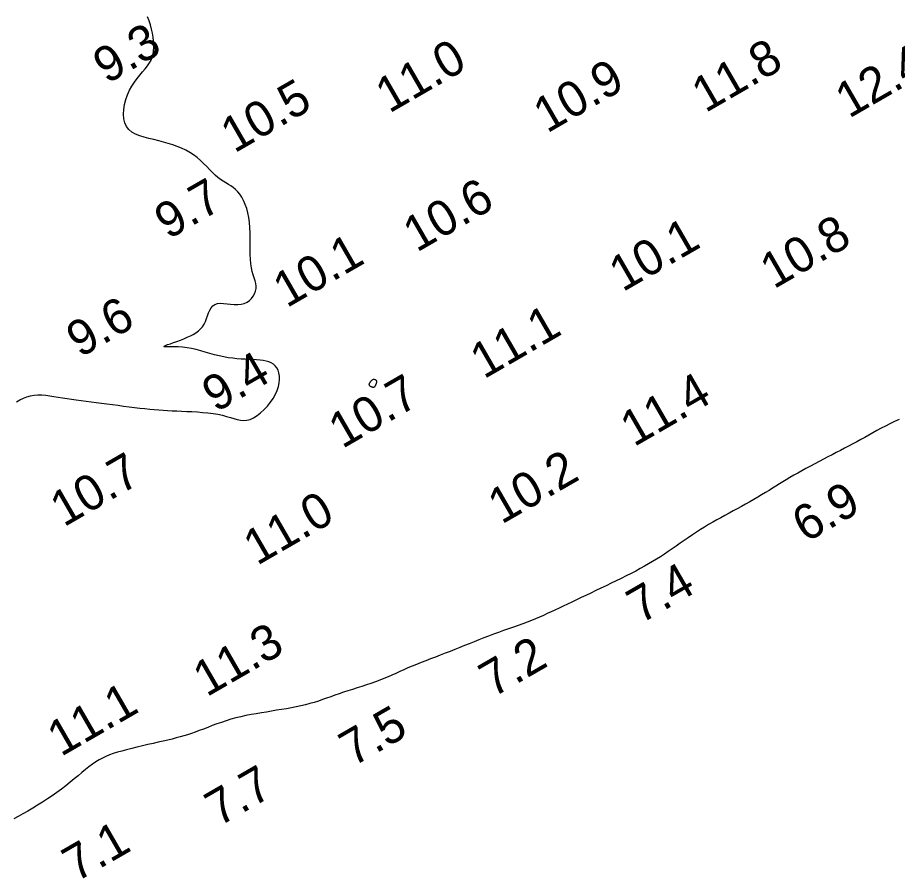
# Model space of a CAD drawing. Extents: x 3024098 to 3056816, y 418252 to 509144.
# Drawn here: x 3024802.5 to 3024927, y 428293.1 to 428414.9 of the extents above; entities that cross this region are included whole.
import ezdxf

# ---------------------------------------------------------------- set-up
doc = ezdxf.new("R2010")
doc.units = 0
doc.layers.add('V-CHAN-CONT-EL10', color=7, linetype='Continuous')
doc.layers.add('V-TOPO-SOUN-0911', color=7, linetype='Continuous')

msp = doc.modelspace()

# ---------------------------------------------------------------- linework, layer by layer
at = {"layer": 'V-CHAN-CONT-EL10'}
for points in [[(3024802.33, 428360.55), (3024802.82, 428360.83), (3024803.31, 428361.08), (3024803.81, 428361.28), (3024804.32, 428361.43), (3024804.84, 428361.52), (3024805.37, 428361.56), (3024805.91, 428361.55), (3024806.47, 428361.5), (3024807.05, 428361.42), (3024807.63, 428361.33), (3024808.23, 428361.23), (3024808.85, 428361.12), (3024809.48, 428361.02), (3024810.13, 428360.92), (3024810.79, 428360.84), (3024811.47, 428360.75), (3024812.17, 428360.66), (3024812.88, 428360.57), (3024813.61, 428360.48), (3024814.36, 428360.39), (3024815.13, 428360.28), (3024815.92, 428360.18), (3024816.71, 428360.07), (3024817.49, 428359.96), (3024818.27, 428359.86), (3024819.04, 428359.76), (3024819.78, 428359.67), (3024820.5, 428359.59), (3024821.18, 428359.52), (3024821.83, 428359.46), (3024822.47, 428359.42), (3024823.09, 428359.37), (3024823.72, 428359.34), (3024824.36, 428359.3), (3024825.01, 428359.27), (3024825.7, 428359.24), (3024826.42, 428359.21), (3024827.16, 428359.17), (3024827.92, 428359.12), (3024828.67, 428359.06), (3024829.42, 428358.99), (3024830.14, 428358.9), (3024830.83, 428358.79), (3024831.47, 428358.66), (3024832.05, 428358.5), (3024832.59, 428358.34), (3024833.09, 428358.18), (3024833.56, 428358.05), (3024834.02, 428357.96), (3024834.46, 428357.92), (3024834.92, 428357.96), (3024835.39, 428358.08), (3024835.88, 428358.3), (3024836.38, 428358.62), (3024836.88, 428359.01), (3024837.38, 428359.46), (3024837.84, 428359.96), (3024838.27, 428360.5), (3024838.66, 428361.05), (3024838.98, 428361.62), (3024839.22, 428362.18), (3024839.4, 428362.72), (3024839.51, 428363.24), (3024839.56, 428363.74), (3024839.54, 428364.21), (3024839.47, 428364.64), (3024839.35, 428365.03), (3024839.17, 428365.36), (3024838.95, 428365.65), (3024838.69, 428365.88), (3024838.38, 428366.06), (3024838.04, 428366.21), (3024837.66, 428366.32), (3024837.24, 428366.4), (3024836.79, 428366.46), (3024836.31, 428366.5), (3024835.8, 428366.54), (3024835.26, 428366.56), (3024834.7, 428366.59), (3024834.12, 428366.62), (3024833.53, 428366.66), (3024832.92, 428366.72), (3024832.29, 428366.8), (3024831.65, 428366.92), (3024831.01, 428367.06), (3024830.36, 428367.23), (3024829.7, 428367.41), (3024829.05, 428367.6), (3024828.4, 428367.79), (3024827.74, 428367.96), (3024827.1, 428368.11), (3024826.46, 428368.22), (3024825.83, 428368.29), (3024825.23, 428368.33), (3024824.68, 428368.34), (3024824.19, 428368.34), (3024823.77, 428368.33), (3024823.45, 428368.33), (3024823.25, 428368.34), (3024823.17, 428368.38), (3024823.24, 428368.44), (3024823.43, 428368.53), (3024823.72, 428368.65), (3024824.1, 428368.79), (3024824.54, 428368.95), (3024825.02, 428369.12), (3024825.52, 428369.3), (3024826.02, 428369.49), (3024826.49, 428369.69), (3024826.93, 428369.89), (3024827.35, 428370.1), (3024827.73, 428370.33), (3024828.08, 428370.59), (3024828.39, 428370.87), (3024828.67, 428371.18), (3024828.89, 428371.53), (3024829.08, 428371.92), (3024829.24, 428372.33), (3024829.38, 428372.75), (3024829.52, 428373.16), (3024829.68, 428373.54), (3024829.87, 428373.88), (3024830.1, 428374.15), (3024830.39, 428374.35), (3024830.75, 428374.46), (3024831.16, 428374.5), (3024831.62, 428374.48), (3024832.12, 428374.44), (3024832.63, 428374.38), (3024833.14, 428374.34), (3024833.64, 428374.33), (3024834.12, 428374.37), (3024834.56, 428374.49), (3024834.95, 428374.67), (3024835.3, 428374.91), (3024835.6, 428375.19), (3024835.84, 428375.51), (3024836.03, 428375.85), (3024836.16, 428376.21), (3024836.23, 428376.58), (3024836.23, 428376.94), (3024836.18, 428377.31), (3024836.08, 428377.69), (3024835.97, 428378.09), (3024835.83, 428378.53), (3024835.7, 428379), (3024835.58, 428379.52), (3024835.49, 428380.09), (3024835.43, 428380.73), (3024835.4, 428381.42), (3024835.4, 428382.15), (3024835.4, 428382.91), (3024835.4, 428383.68), (3024835.39, 428384.45), (3024835.36, 428385.21), (3024835.3, 428385.95), (3024835.2, 428386.65), (3024835.07, 428387.32), (3024834.9, 428387.94), (3024834.7, 428388.51), (3024834.47, 428389.04), (3024834.21, 428389.52), (3024833.94, 428389.94), (3024833.64, 428390.3), (3024833.33, 428390.61), (3024833.01, 428390.88), (3024832.67, 428391.11), (3024832.32, 428391.33), (3024831.96, 428391.54), (3024831.59, 428391.77), (3024831.22, 428392.02), (3024830.84, 428392.3), (3024830.46, 428392.64), (3024830.06, 428393.02), (3024829.66, 428393.43), (3024829.25, 428393.85), (3024828.81, 428394.29), (3024828.36, 428394.72), (3024827.88, 428395.13), (3024827.38, 428395.52), (3024826.84, 428395.86), (3024826.28, 428396.18), (3024825.69, 428396.46), (3024825.08, 428396.71), (3024824.45, 428396.94), (3024823.79, 428397.14), (3024823.13, 428397.33), (3024822.45, 428397.51), (3024821.76, 428397.67), (3024821.07, 428397.83), (3024820.4, 428398.01), (3024819.77, 428398.21), (3024819.19, 428398.46), (3024818.67, 428398.75), (3024818.23, 428399.1), (3024817.88, 428399.54), (3024817.64, 428400.05), (3024817.5, 428400.63), (3024817.46, 428401.27), (3024817.5, 428401.94), (3024817.61, 428402.63), (3024817.79, 428403.33), (3024818.04, 428404), (3024818.33, 428404.65), (3024818.66, 428405.24), (3024819.03, 428405.79), (3024819.41, 428406.31), (3024819.79, 428406.79), (3024820.17, 428407.25), (3024820.53, 428407.68), (3024820.86, 428408.11), (3024821.14, 428408.53), (3024821.37, 428408.94), (3024821.54, 428409.36), (3024821.66, 428409.79), (3024821.74, 428410.23), (3024821.77, 428410.69), (3024821.77, 428411.16), (3024821.73, 428411.66), (3024821.66, 428412.19), (3024821.57, 428412.74), (3024821.44, 428413.32), (3024821.29, 428413.9), (3024821.1, 428414.47), (3024820.87, 428415.03)], [(3024927.21, 428358.08), (3024926.55, 428357.77), (3024925.92, 428357.45), (3024925.3, 428357.13), (3024924.69, 428356.81), (3024924.09, 428356.48), (3024923.51, 428356.16), (3024922.93, 428355.84), (3024922.36, 428355.52), (3024921.79, 428355.21), (3024921.22, 428354.9), (3024920.65, 428354.6), (3024920.08, 428354.29), (3024919.5, 428353.99), (3024918.92, 428353.68), (3024918.33, 428353.38), (3024917.74, 428353.07), (3024917.13, 428352.76), (3024916.52, 428352.44), (3024915.9, 428352.11), (3024915.28, 428351.78), (3024914.66, 428351.46), (3024914.04, 428351.13), (3024913.45, 428350.8), (3024912.87, 428350.48), (3024912.31, 428350.16), (3024911.77, 428349.84), (3024911.26, 428349.54), (3024910.77, 428349.23), (3024910.28, 428348.93), (3024909.79, 428348.63), (3024909.31, 428348.32), (3024908.81, 428348.02), (3024908.3, 428347.71), (3024907.77, 428347.39), (3024907.22, 428347.07), (3024906.66, 428346.74), (3024906.08, 428346.41), (3024905.5, 428346.08), (3024904.91, 428345.76), (3024904.32, 428345.43), (3024903.73, 428345.11), (3024903.15, 428344.79), (3024902.57, 428344.47), (3024901.99, 428344.16), (3024901.42, 428343.84), (3024900.84, 428343.51), (3024900.27, 428343.18), (3024899.7, 428342.83), (3024899.12, 428342.47), (3024898.55, 428342.1), (3024897.97, 428341.72), (3024897.39, 428341.32), (3024896.82, 428340.93), (3024896.25, 428340.53), (3024895.68, 428340.13), (3024895.12, 428339.74), (3024894.56, 428339.36), (3024894, 428339), (3024893.45, 428338.64), (3024892.9, 428338.3), (3024892.34, 428337.96), (3024891.77, 428337.62), (3024891.18, 428337.29), (3024890.58, 428336.95), (3024889.95, 428336.61), (3024889.29, 428336.27), (3024888.61, 428335.92), (3024887.91, 428335.57), (3024887.19, 428335.22), (3024886.47, 428334.87), (3024885.75, 428334.52), (3024885.02, 428334.17), (3024884.31, 428333.83), (3024883.6, 428333.49), (3024882.91, 428333.16), (3024882.23, 428332.84), (3024881.57, 428332.53), (3024880.92, 428332.22), (3024880.29, 428331.92), (3024879.69, 428331.64), (3024879.1, 428331.36), (3024878.52, 428331.09), (3024877.97, 428330.83), (3024877.42, 428330.58), (3024876.88, 428330.33), (3024876.33, 428330.09), (3024875.77, 428329.85), (3024875.19, 428329.61), (3024874.59, 428329.38), (3024873.97, 428329.14), (3024873.31, 428328.9), (3024872.64, 428328.66), (3024871.95, 428328.42), (3024871.25, 428328.17), (3024870.55, 428327.92), (3024869.84, 428327.67), (3024869.14, 428327.41), (3024868.45, 428327.14), (3024867.76, 428326.87), (3024867.08, 428326.6), (3024866.4, 428326.32), (3024865.72, 428326.05), (3024865.04, 428325.77), (3024864.36, 428325.5), (3024863.68, 428325.23), (3024862.99, 428324.96), (3024862.29, 428324.7), (3024861.6, 428324.43), (3024860.92, 428324.17), (3024860.24, 428323.92), (3024859.58, 428323.66), (3024858.94, 428323.4), (3024858.31, 428323.15), (3024857.72, 428322.89), (3024857.14, 428322.63), (3024856.58, 428322.37), (3024856.02, 428322.12), (3024855.46, 428321.86), (3024854.9, 428321.62), (3024854.33, 428321.38), (3024853.74, 428321.14), (3024853.12, 428320.92), (3024852.48, 428320.7), (3024851.84, 428320.48), (3024851.18, 428320.28), (3024850.52, 428320.07), (3024849.86, 428319.86), (3024849.22, 428319.65), (3024848.59, 428319.45), (3024847.97, 428319.23), (3024847.38, 428319.02), (3024846.79, 428318.81), (3024846.21, 428318.6), (3024845.63, 428318.4), (3024845.05, 428318.2), (3024844.45, 428318.01), (3024843.85, 428317.84), (3024843.22, 428317.67), (3024842.57, 428317.52), (3024841.91, 428317.38), (3024841.24, 428317.25), (3024840.55, 428317.12), (3024839.85, 428317), (3024839.14, 428316.89), (3024838.42, 428316.77), (3024837.7, 428316.65), (3024836.98, 428316.53), (3024836.25, 428316.41), (3024835.52, 428316.28), (3024834.8, 428316.14), (3024834.08, 428315.98), (3024833.38, 428315.81), (3024832.68, 428315.62), (3024831.99, 428315.41), (3024831.32, 428315.19), (3024830.66, 428314.96), (3024830.02, 428314.72), (3024829.39, 428314.48), (3024828.78, 428314.24), (3024828.19, 428314.02), (3024827.62, 428313.81), (3024827.08, 428313.61), (3024826.54, 428313.44), (3024826.01, 428313.28), (3024825.47, 428313.12), (3024824.92, 428312.98), (3024824.34, 428312.83), (3024823.73, 428312.68), (3024823.09, 428312.53), (3024822.39, 428312.37), (3024821.66, 428312.21), (3024820.91, 428312.04), (3024820.14, 428311.86), (3024819.38, 428311.68), (3024818.63, 428311.5), (3024817.91, 428311.32), (3024817.23, 428311.13), (3024816.61, 428310.95), (3024816.03, 428310.76), (3024815.49, 428310.57), (3024814.98, 428310.36), (3024814.49, 428310.13), (3024814.02, 428309.87), (3024813.55, 428309.59), (3024813.07, 428309.27), (3024812.59, 428308.91), (3024812.09, 428308.51), (3024811.57, 428308.09), (3024811.04, 428307.64), (3024810.49, 428307.18), (3024809.92, 428306.7), (3024809.32, 428306.22), (3024808.7, 428305.74), (3024808.05, 428305.26), (3024807.38, 428304.8), (3024806.7, 428304.34), (3024806.01, 428303.89), (3024805.31, 428303.46), (3024804.62, 428303.04), (3024803.93, 428302.64), (3024803.25, 428302.25), (3024802.59, 428301.88), (3024801.95, 428301.53)]]:
    msp.add_lwpolyline(points, dxfattribs=at)
msp.add_lwpolyline([(3024853.01, 428362.71), (3024853.04, 428362.73), (3024853.06, 428362.75), (3024853.08, 428362.77), (3024853.1, 428362.8), (3024853.12, 428362.84), (3024853.14, 428362.87), (3024853.16, 428362.91), (3024853.18, 428362.96), (3024853.2, 428363.01), (3024853.22, 428363.06), (3024853.24, 428363.12), (3024853.25, 428363.17), (3024853.27, 428363.22), (3024853.29, 428363.27), (3024853.3, 428363.32), (3024853.31, 428363.36), (3024853.32, 428363.39), (3024853.33, 428363.43), (3024853.33, 428363.46), (3024853.33, 428363.49), (3024853.31, 428363.51), (3024853.29, 428363.54), (3024853.26, 428363.57), (3024853.23, 428363.6), (3024853.18, 428363.63), (3024853.12, 428363.66), (3024853.06, 428363.69), (3024852.99, 428363.7), (3024852.93, 428363.71), (3024852.85, 428363.71), (3024852.78, 428363.7), (3024852.71, 428363.67), (3024852.64, 428363.63), (3024852.58, 428363.58), (3024852.51, 428363.52), (3024852.46, 428363.46), (3024852.4, 428363.39), (3024852.35, 428363.33), (3024852.31, 428363.26), (3024852.27, 428363.2), (3024852.24, 428363.15), (3024852.22, 428363.1), (3024852.21, 428363.05), (3024852.2, 428363.01), (3024852.21, 428362.96), (3024852.23, 428362.92), (3024852.25, 428362.88), (3024852.29, 428362.85), (3024852.34, 428362.81), (3024852.39, 428362.77), (3024852.45, 428362.74), (3024852.52, 428362.71), (3024852.58, 428362.69), (3024852.64, 428362.67), (3024852.7, 428362.65), (3024852.75, 428362.65), (3024852.79, 428362.64), (3024852.83, 428362.64), (3024852.87, 428362.64), (3024852.9, 428362.65), (3024852.94, 428362.66), (3024852.96, 428362.67), (3024852.99, 428362.69)], close=True, dxfattribs=at)

# ---------------------------------------------------------------- texts
at = {"layer": 'V-TOPO-SOUN-0911'}
for s, p in [('9.3', (3024815.1, 428405.47)), ('11.0 ', (3024855.07, 428401.33)), ('11.8 ', (3024899.81, 428401.4)), ('12.4 ', (3024920.12, 428400.61)), ('10.9 ', (3024877.4, 428398.51)), ('10.5 ', (3024833.16, 428395.69)), ('9.7', (3024823.79, 428383.46)), ('10.6 ', (3024858.96, 428381.65)), ('10.8 ', (3024909.49, 428376.46)), ('10.1 ', (3024888.11, 428376.05)), ('10.1 ', (3024840.57, 428373.79)), ('9.6', (3024811.32, 428366.73)), ('11.1 ', (3024868.46, 428363.72)), ('9.4', (3024830.52, 428358.98)), ('10.7 ', (3024848.43, 428353.86)), ('11.4 ', (3024889.7, 428354.12)), ('10.7 ', (3024809.03, 428342.77)), ('10.2 ', (3024870.97, 428343.16)), ('6.9', (3024914.01, 428340.55)), ('11.0 ', (3024836.37, 428337.32)), ('7.4', (3024890.62, 428329.06)), ('11.3 ', (3024829.24, 428318.72)), ('7.2', (3024869.72, 428318.63)), ('11.1 ', (3024808.62, 428310.27)), ('7.5', (3024849.93, 428308.85)), ('7.7', (3024830.94, 428300.36)), ('7.1', (3024810.75, 428292.5))]:
    msp.add_text(s, height=5, rotation=30, dxfattribs=at).set_placement(p)

doc.saveas('drawing.dxf')
